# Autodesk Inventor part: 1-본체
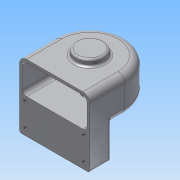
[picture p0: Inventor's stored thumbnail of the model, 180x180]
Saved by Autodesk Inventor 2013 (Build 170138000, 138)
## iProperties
Created: 2015-02
Part Number: 1-본체
Material: 알루미늄 6061
Document SubType Name: Modeling
Designer: Administrator
Density: 2.40731 g/cm^3
Mass: 511.357 g
Surface Area: 706.391 cm^2
Volume: 212.418 cm^3
Author: Administrator
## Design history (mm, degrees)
sketch "스케치1"
  geometry: L1 (-50, 0)-(-50, -50); L2 (-50, -50)-(50, -50); L3 (50, -50)-(50, 0); A1 r 50 centre (0, 0) between (-50, 0) and (50, 0); 1 further point
  constraints: 6 end point, 2 point on circle, 2 tangent, 1 centre point, 1 coincident, 1 horizontal, 1 parallel, 1 vertical
  dimensions: "d0" = 100 diameter of A1; "d2" = 50 distance from line of L2 point (0, 0)
extrude "돌출1" new body sketch "스케치1" distance "d3" = 50; taper "d4" = 0 deg
sketch "스케치2"
  geometry: L1 (-50, 0)-(-50, -50) reference; L2 (-50, -50)-(50, -50) reference; L3 (50, -50)-(50, 0) reference; L4 (-50, -50)-(50, -50); L5 (50, -50)-(50, -20); L6 (50, -20)-(-50, -20); L7 (-50, -20)-(-50, -50); L8 (-50, -50)-(50, -20); L9 (50, -50)-(-50, -20); 1 further point
  constraints: 12 end point, 3 collinear, 2 midpoint, 2 parallel, 1 horizontal, 1 perpendicular
  dimensions: "d5" = 30 distance between parallel lines of L2 L6
extrude "돌출2" join sketch "스케치2" distance "d6" = 95; taper "d7" = 0 deg
sketch "스케치3"
  geometry: L1 (-50, -20)-(50, -20) reference; A1 r 50 centre (0, 0) between (50, 0) and (-50, 0) reference; A2 r 40 centre (0, 0) between (-34.641, -20) and (34.641, -20)
  constraints: 2 point on circle, 2 point on line, 1 centre point, 1 coincident
  dimensions: "d8" = 80 diameter of A2
extrude "돌출3" cut sketch "스케치3" stored distance "d10" = 95; taper "d11" = 0 deg
sketch "스케치4"
  geometry: C1 r 25 at (0, 0); A1 r 50 centre (0, 0) between (50, 0) and (-50, 0) reference
  constraints: 1 centre point, 1 coincident
  dimensions: "d12" = 50 diameter of C1
extrude "돌출4" join sketch "스케치4" distance "d14" = 10; taper "d15" = -20 deg
sketch "스케치5"
  geometry: C1 r 20 at (0, 0); A1 r 50 centre (0, 0) between (50, 0) and (-50, 0) reference
  constraints: 1 centre point, 1 coincident
  dimensions: "d16" = 40 diameter of C1
extrude "돌출5" join sketch "스케치5" distance "d18" = 9; taper "d19" = 0 deg
node "작업 평면1"
sketch "스케치7"
  geometry: L1 (-50, 0)-(-50, -50) reference; L2 (-50, -50)-(50, -50) reference; L3 (50, -50)-(50, 0) reference; L4 (46, 0)-(46, -50); L5 (-46, -50)-(-46, 0); L6 (-46, -50)-(46, -50); A1 r 50 centre (0, 0) between (50, 0) and (-50, 0) reference; A2 r 46 centre (0, 0) between (46, 0) and (-46, 0); 1 further point
  constraints: 6 end point, 2 point on circle, 2 point on line, 1 centre point, 1 collinear
  dimensions: "d21" = 4 radial gap between concentric circles of A1 A2; "d24" = 4 distance between parallel lines of L5 L1; "d25" = 4 distance between parallel lines of L3 L4
extrude "돌출6" cut sketch "스케치7" distance "d22" = 42; taper "d23" = 0 deg
hole "구멍1" diameter "d28" = 20; stored, may be unused: countersink angle "d32" = 90 deg, drill point angle "d34" = 0 deg; dims "d26" = 10, "d27" = 10, "d29" = 6, "d30" = 28, "d31" = 10, "d33" = 14
sketch "스케치8"
  geometry: A1 r 46 centre (0, 0) between (46, 0) and (-46, 0) reference; 1 further point
  constraints: 1 coincident
hole "구멍2" sketch "스케치8" at (0, 0) diameter "d35" = 20; stored, may be unused: countersink angle "d39" = 90 deg, drill point angle "d41" = 0 deg; dims "d36" = 6, "d37" = 28, "d38" = 8, "d40" = 10
sketch "스케치9"
  geometry: L1 (100, -95)-(0, -95) reference; L2 (91.75, -86)-(8.25, -86); L3 (8.25, -86)-(8.25, -53); L4 (8.25, -53)-(91.75, -53); L5 (91.75, -53)-(91.75, -86); L6 (91.75, -86)-(8.25, -53); L7 (8.25, -86)-(91.75, -53); 7 further points
  constraints: 12 end point, 4 coincident, 3 midpoint, 2 parallel, 1 horizontal, 1 perpendicular, 1 vertical alignment
  dimensions: "d42" = 33 distance of L2.end L3.end; "d44" = 83.5 distance of L2.start L2.end; "d45" = 9 distance between parallel lines of L2 L1
hole "구멍3" sketch "스케치9" at (8.25, -86), (8.25, -53), (91.75, -86), (91.75, -53) diameter "d46" = 5.134; stored, may be unused: countersink angle "d50" = 90 deg, drill point angle "d52" = 118 deg; dims "d47" = 10, "d48" = 28, "d49" = 8, "d51" = 13
sketch "스케치10"
  geometry: C1 r 14 at (0, 0) reference; C2 r 21.36 at (0, 0) reference; A1 r 18 centre (0, 0) between (0, 18) and (18, 0); 2 further points
  constraints: 4 point on circle, 2 horizontal alignment, 2 vertical alignment, 1 centre point, 1 coincident
  dimensions: "d53" = 36 diameter of A1
hole "구멍4" sketch "스케치10" at (0, 18), (18, 0), (-18, 0), (0, -18) diameter "d55" = 2.459; stored, may be unused: countersink angle "d59" = 90 deg, drill point angle "d61" = 118 deg; dims "d56" = 6, "d57" = 28, "d58" = 8, "d60" = 9
fillet "모깎기1" dims "d62" = 10
fillet "모깎기2" dims "d63" = 3
node "작업 평면2"
sketch "스케치11"
  geometry: L1 (-40, 50)-(40, 50) reference; 3 further points
  constraints: 1 midpoint, 1 vertical alignment, 1 other
  dimensions: "d64" = 25 distance from line of point (0, 25) L1
feature "엠보싱1" sketch "스케치11" dims "d0" = 100, "d2" = 50, "d65" = 0.5, "d66" = 0
fillet "모깎기3" dims "d67" = 6
fillet "모깎기4" dims "d68" = 0.3
chamfer "모따기1" distance "d69" = 1; stored, may be unused: second distance "d70" = 2, angle "d71" = 45 deg
fillet "모깎기5" dims "d72" = 3
node "솔리드1"
other parameters: "d20" = -4
